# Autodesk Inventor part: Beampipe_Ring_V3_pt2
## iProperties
Shininess: 64.0
Length Units: 11269
Angle Units: 11279
Time Units: 11290
Mass Units: 11283
Length Display Precision: 3
Angle Display Precision: 2
Compacted: True
Part Number: Beampipe_Ring_V3_pt2
Document SubType Name: Modeling
Created: 2004-08
Designer: John Blackburn
Manufacturer: Standard
Standards Organization: Custom
Material: Aluminum-6061
Density: 0.0
Volumn: 0.0
Area: 0.0
PropertySet Name: Model Information
Control State: 0
Master: False
Checked Out: False
Author: John Blackburn
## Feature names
1. Extrusion1
2. Extrusion3
3. Split1
4. Hole4
5. Hole5
6. Hole8
7. Hole9
8. Hole10
